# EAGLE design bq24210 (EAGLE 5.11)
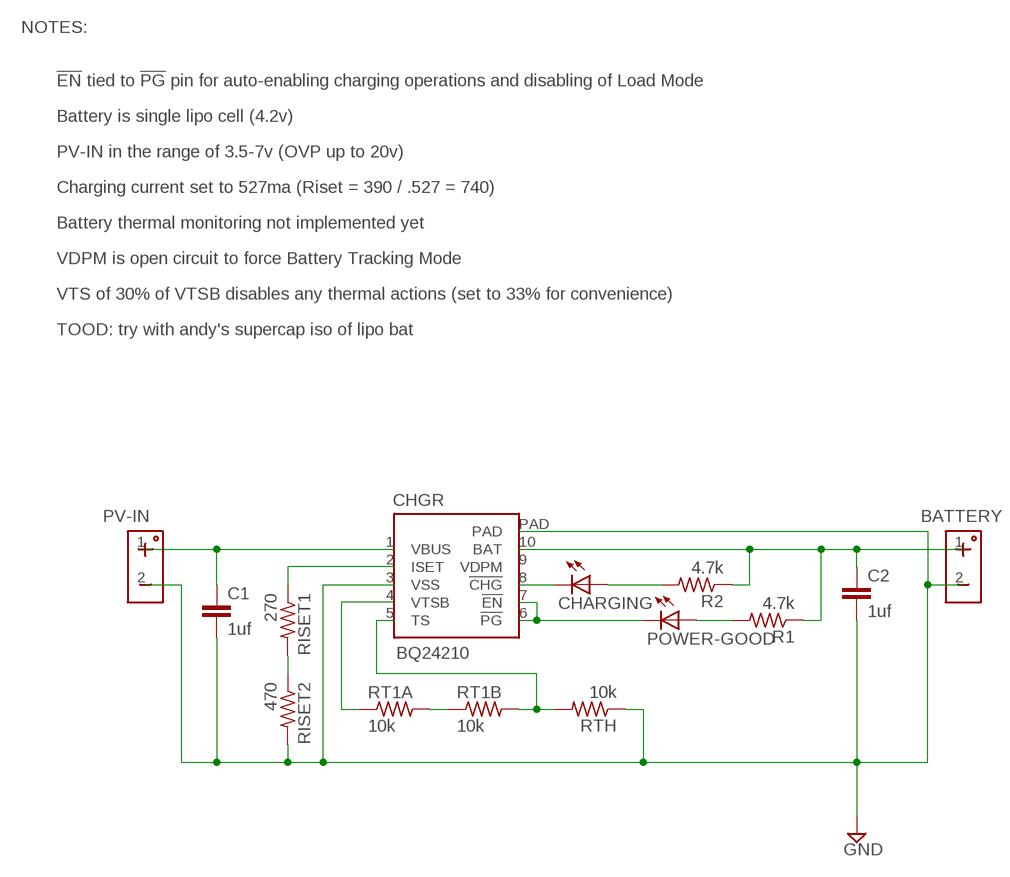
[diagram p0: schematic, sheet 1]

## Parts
BATTERY  HEADER-POWER  [HEADER-POWER-PTH]
C1  1uf  C-EUC0805  [C0805]
C2  1uf  C-EUC0805  [C0805]
CHARGING  LEDCHIPLED_0805  [CHIPLED_0805]
CHGR  BQ24210  [WSON10]
POWER-GOOD  LEDCHIPLED_0805  [CHIPLED_0805]
PV-IN  HEADER-POWER  [HEADER-POWER-PTH]
R1  4.7k  R-US_R0805  [R0805]
R2  4.7k  R-US_R0805  [R0805]
RISET1  270  R-US_R0805  [R0805]
RISET2  470  R-US_R1206  [R1206]
RT1A  10k  R-US_R0805  [R0805]
RT1B  10k  R-US_R0805  [R0805]
RTH  10k  R-US_R0805  [R0805]

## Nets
GND: BATTERY.2 C1.2 C2.2 CHGR.3(VSS) CHGR.PAD PV-IN.2 RISET2.2 RTH.1
N$1: BATTERY.1 C2.1 CHGR.10(BAT) R1.1 R2.1
N$2: CHARGING.C CHGR.8(!CHG)
N$3: CHARGING.A R2.2
N$4: C1.1 CHGR.1(VBUS) PV-IN.1
N$5: CHGR.6(!PG) CHGR.7(!EN) POWER-GOOD.C
N$6: POWER-GOOD.A R1.2
N$7: CHGR.2(ISET) RISET1.1
N$8: RISET1.2 RISET2.1
N$9: RT1A.2 RT1B.1
N$10: CHGR.5(TS) RT1B.2 RTH.2
N$11: CHGR.4(VTSB) RT1A.1
Unconnected: CHGR.9(VDPM)

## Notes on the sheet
- NOTES:
- !EN! tied to !PG! pin for auto-enabling charging operations and disabling of Load Mode
- Battery is single lipo cell (4.2v)
- PV-IN in the range of 3.5-7v (OVP up to 20v)
- Charging current set to 527ma (Riset = 390 / .527 = 740)
- Battery thermal monitoring not implemented yet
- VDPM is open circuit to force Battery Tracking Mode
- VTS of 30% of VTSB disables any thermal actions (set to 33% for convenience)
- TOOD: try with andy's supercap iso of lipo bat

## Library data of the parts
BATTERY PV-IN = trl:HEADER-POWER
C1 C2 = rcl:C-EU: CAPACITOR, European symbol
CHARGING POWER-GOOD = led:LED: LED
CHGR = trl:BQ24210
R1 R2 RISET1 RISET2 RT1A RT1B RTH = rcl:R-US_: RESISTOR, American symbol

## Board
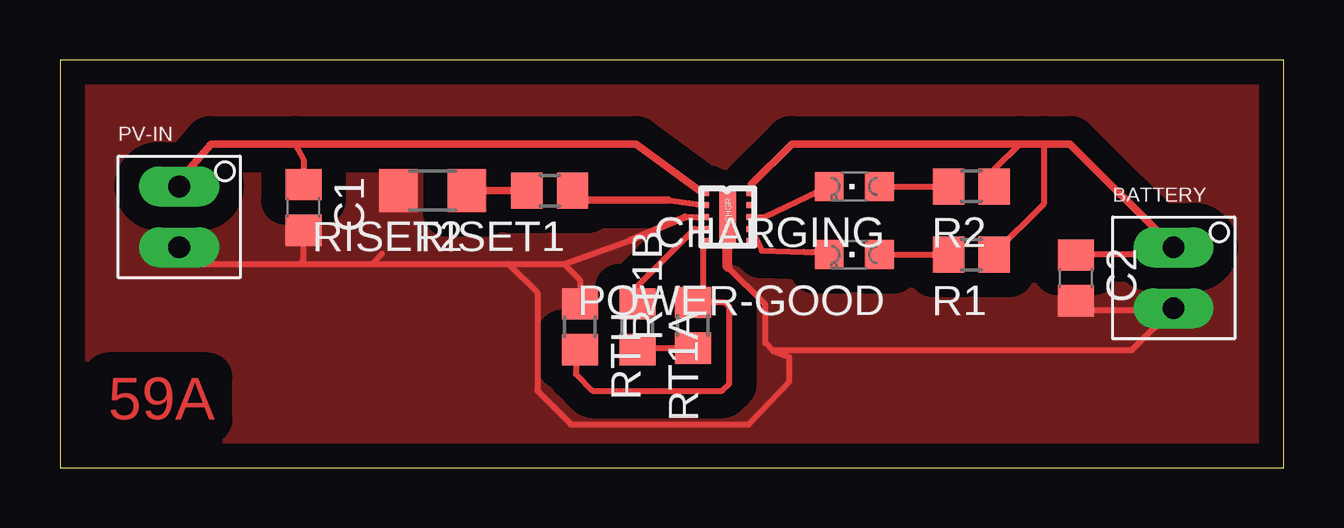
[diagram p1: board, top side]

Size 51 x 17 mm. Coordinates in mm from the lower left corner, seen from the top.
Outline: 0,0 51,0 51,17 0,17 0,0
Copper layers (1*16): Top 0.035mm / dielectric 1.5mm / Bottom 0.035mm
Design rules "default": minimum track width 10mil, minimum drill 0.6mm, track to track 8mil, track to pad 8mil, pad to pad 8mil, via to via 8mil, smd to smd 8mil, copper to edge 40mil, drill to drill 8mil, minimum pad ring 10mil, minimum via ring 8mil, stop-mask expansion 4mil, vias tented up to drill 0mil, thermal gap 10mil

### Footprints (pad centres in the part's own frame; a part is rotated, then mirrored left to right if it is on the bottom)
HEADER-POWER-PTH = drill 0.9 pad 1.676 long: 1 0,1.27; 2 0,-1.27
C0805 = smd 1.3 x 1.5: 1 -0.95,0; 2 0.95,0
CHIPLED_0805 = smd 1.2 x 1.2: A 0,-1.05; C 0,1.05
WSON10 = smd 0.25 x 0.45: 1 -1,-1; 2 -0.5,-1; 3 0,-1; 4 0.5,-1; 5 1,-1; 6 1,1; 7 0.5,1; 8 0,1; 9 -0.5,1; 10 -1,1 | smd 2.25 x 0.7: PAD 0,0
R0805 = smd 1.3 x 1.5: 1 -0.95,0; 2 0.95,0
R1206 = smd 1.6 x 1.803: 1 -1.422,0; 2 1.422,0

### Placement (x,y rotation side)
BATTERY  46.42,7.91 0 top
C1  10.15,10.85 270 top
C2  42.34,7.91 270 top
CHARGING  33.11,11.72 90 top
CHGR  27.83,10.45 270 top
POWER-GOOD  33.11,8.88 90 top
PV-IN  4.97,10.45 0 top
R1  37.99,8.88 180 top
R2  37.99,11.72 180 top
RISET1  20.41,11.55 180 top
RISET2  15.53,11.55 180 top
RT1A  24.07,5.87 270 top
RT1B  26.38,5.93 90 top
RTH  21.67,5.87 270 top

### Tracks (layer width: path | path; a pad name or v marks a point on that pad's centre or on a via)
GND
  Top 0.254: 26.05,10.45 CHGR.3 | 10,8.5 5.65,8.5 PV-IN.2 | 10,8.5 13,8.5 | 13,8.5 18.7,8.5 | 18.7,8.5 21,8.5 | 21,8.5 23.8,9.5 | 13,8.5 13.41,8.91 | C1.2 10.15,8.65 10,8.5 | RTH.1 21.67,7.83 21,8.5 | 29.74,4.85 30.4,4.6 30.4,3.6 28.7,1.8 21.3,1.8 19.9,3.2 19.9,7.3 18.7,8.5 | 29.74,4.85 29.8,4.9 44.68,4.9 BATTERY.2 46.34,6.56 42.34,6.56 C2.2 | 27.83,8.37 29.4,6.8 29.4,5.19 29.74,4.85
  Top 0.305: 23.8,9.5 26.05,10.45
  Top 0.406: 27.83,8.37 CHGR.PAD
  pour Top (isolate 1.016, no thermals): 0,17 51,17 51,0 0,0
N$1
  Top 0.254: C2.1 42.32,8.88 46.12,8.88 BATTERY.1 | R1.1 38.94,8.94 41,11 41,13.5 | R2.1 38.94,12.44 40,13.5
  Top 0.305: CHGR.10 28.83,11.83 30.5,13.5 40,13.5 41,13.5 42.1,13.5 BATTERY.1
N$2
  Top 0.254: CHGR.8 29.39,10.45 CHARGING.C
N$3
  Top 0.254: CHARGING.A R2.2
N$4
  Top 0.254: 26.65,11.55 CHGR.1 | 10.65,12 C1.1 10.15,12.85 9.8,13.5
  Top 0.305: PV-IN.1 4.97,11.97 6.3,13.5 9.8,13.5 24,13.5 26.65,11.55
N$5
  Top 0.254: POWER-GOOD.C 31.68,9 31,9 29.25,9.05 CHGR.7 CHGR.6
N$6
  Top 0.254: POWER-GOOD.A R1.2
N$7
  Top 0.254: 25.35,11.15 CHGR.2
  Top 0.305: 25.35,11.15 21.76,11.15 RISET1.1
N$8
  Top 0.305: RISET2.1 RISET1.2
N$9
  Top 0.254: RT1B.1 24.13,4.98 RT1A.2
N$10
  Top 0.254: CHGR.5 26.83,7.33 RT1B.2 27.72,6.88 27.9,6.7 27.9,3.5 27.6,3.2 22.2,3.2 21.5,3.9 21.5,4.75 RTH.2
N$11
  Top 0.254: CHGR.4 26.45,9.95 24.1,7.6 24.1,6.85 RT1A.1

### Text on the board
Top: 59A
